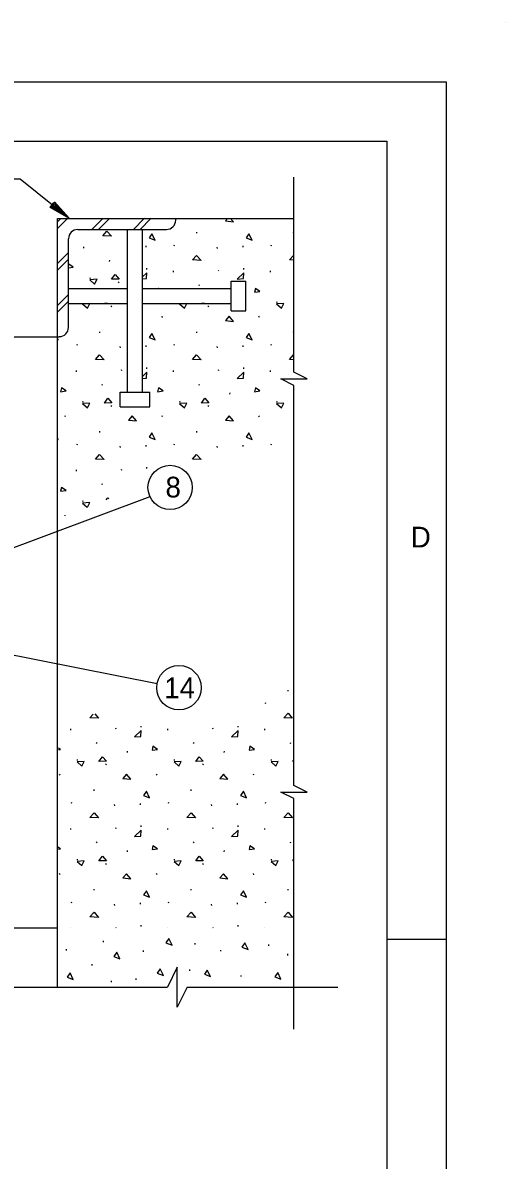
# Model space of a CAD drawing. Extents: x -0.2 to 13.5, y -0.2 to 9.5.
# Drawn here: x 12.14 to 13.5, y 6.294 to 9.5 of the extents above; entities that cross this region are included whole.
import ezdxf

# ---------------------------------------------------------------- set-up
doc = ezdxf.new("R2010")
doc.units = 0
for name, color, linetype in [('Level 1', 7, 'Continuous'), ('Level 10', 7, 'Continuous'), ('Level 13', 7, 'Continuous'), ('Level 2', 7, 'Continuous'), ('Level 3', 7, 'Continuous'), ('Level 50', 7, 'Continuous')]:
    doc.layers.add(name, color=color, linetype=linetype)

msp = doc.modelspace()

# ---------------------------------------------------------------- linework, layer by layer
at = {"layer": 'Level 1'}
msp.add_line((13.1667, 6.9167), (13.3333, 6.9167), dxfattribs=at)
for points in [[(0, 9.3333), (13.3333, 9.3333), (13.3333, 0), (0, 0)], [(0.5, 9.1667), (13.1667, 9.1667), (13.1667, 0.1667), (0.5, 0.1667)]]:
    msp.add_lwpolyline(points, close=True, dxfattribs=at)
msp.add_lwpolyline([(12.6037, 6.7819), (12.5758, 6.7256), (12.5758, 6.838), (12.5477, 6.7819)], dxfattribs=at)
at = {"layer": 'Level 10'}
for p, q in [((12.6306, 8.9066), (12.6304, 8.9097)), ((12.9039, 8.9066), (12.9037, 8.9097)), ((12.3119, 8.865), (12.3119, 8.8688)), ((12.4882, 8.8671), (12.4882, 8.8709)), ((12.567, 8.8716), (12.5675, 8.8744)), ((12.6888, 8.8641), (12.6877, 8.8679)), ((12.7615, 8.8671), (12.7615, 8.8709)), ((12.8404, 8.8716), (12.8409, 8.8744)), ((12.3844, 8.8275), (12.3858, 8.8304)), ((12.4895, 8.8049), (12.4895, 8.8084)), ((12.5647, 8.7969), (12.5647, 8.8006)), ((12.6925, 8.7994), (12.6915, 8.8021)), ((12.7629, 8.8049), (12.7629, 8.8084)), ((12.838, 8.7969), (12.838, 8.8006)), ((12.3304, 8.7795), (12.3307, 8.7823)), ((12.4102, 8.767), (12.4121, 8.7701)), ((12.6373, 8.7594), (12.6387, 8.7623)), ((12.3898, 8.6989), (12.3917, 8.702)), ((12.6631, 8.6989), (12.665, 8.702)), ((12.8566, 8.7114), (12.8569, 8.7141)), ((12.5344, 8.6696), (12.5327, 8.6729)), ((12.8077, 8.6696), (12.806, 8.6729)), ((12.3573, 8.6261), (12.357, 8.6291)), ((12.6306, 8.6261), (12.6304, 8.6291)), ((12.9039, 8.6261), (12.9037, 8.6291)), ((12.2937, 8.591), (12.2942, 8.5938)), ((12.567, 8.591), (12.5675, 8.5938)), ((12.8404, 8.591), (12.8409, 8.5938)), ((12.4155, 8.5836), (12.4144, 8.5873)), ((12.4882, 8.5866), (12.4882, 8.5903)), ((12.6888, 8.5836), (12.6877, 8.5873)), ((12.7615, 8.5866), (12.7615, 8.5903)), ((12.2914, 8.5163), (12.2914, 8.5201)), ((12.4192, 8.5189), (12.4182, 8.5216)), ((12.4895, 8.5244), (12.4895, 8.5279)), ((12.5647, 8.5163), (12.5647, 8.5201)), ((12.6925, 8.5189), (12.6915, 8.5216)), ((12.7629, 8.5244), (12.7629, 8.5279)), ((12.838, 8.5163), (12.838, 8.5201)), ((12.364, 8.4788), (12.3654, 8.4818)), ((12.6373, 8.4788), (12.6387, 8.4818)), ((12.31, 8.4308), (12.3102, 8.4336)), ((12.5833, 8.4308), (12.5835, 8.4336)), ((12.724, 8.4536), (12.7246, 8.4573)), ((12.8566, 8.4308), (12.8569, 8.4336)), ((12.3898, 8.4183), (12.3917, 8.4214)), ((12.6631, 8.4183), (12.665, 8.4214)), ((12.261, 8.3891), (12.2594, 8.3924)), ((12.5344, 8.3891), (12.5327, 8.3924)), ((12.8077, 8.3891), (12.806, 8.3924)), ((12.3573, 8.3455), (12.357, 8.3486)), ((12.6306, 8.3455), (12.6304, 8.3486)), ((12.2937, 8.3104), (12.2942, 8.3133)), ((12.4155, 8.303), (12.4144, 8.3068)), ((12.4882, 8.306), (12.4882, 8.3098)), ((12.567, 8.3104), (12.5675, 8.3133)), ((12.6888, 8.303), (12.6877, 8.3068)), ((12.7615, 8.306), (12.7615, 8.3098)), ((12.8404, 8.3104), (12.8409, 8.3133)), ((12.4192, 8.2383), (12.4182, 8.241)), ((12.4895, 8.2438), (12.4895, 8.2473)), ((12.2914, 8.2358), (12.2914, 8.2395)), ((12.364, 8.1983), (12.3654, 8.2012)), ((12.31, 8.1503), (12.3102, 8.153)), ((12.8882, 7.616), (12.8879, 7.6191)), ((12.8246, 7.5809), (12.8251, 7.5838)), ((12.2757, 7.5063), (12.2757, 7.51)), ((12.4035, 7.5088), (12.4024, 7.5115)), ((12.4738, 7.5143), (12.4738, 7.5178)), ((12.549, 7.5063), (12.549, 7.51)), ((12.6768, 7.5088), (12.6757, 7.5115)), ((12.7471, 7.5143), (12.7471, 7.5178)), ((12.8223, 7.5063), (12.8223, 7.51)), ((12.3482, 7.4688), (12.3496, 7.4717)), ((12.6216, 7.4688), (12.6229, 7.4717)), ((12.8949, 7.4688), (12.8962, 7.4717)), ((12.435, 7.4436), (12.4356, 7.4472)), ((12.7083, 7.4436), (12.7089, 7.4472)), ((12.2942, 7.4208), (12.2945, 7.4235)), ((12.3741, 7.4083), (12.3759, 7.4114)), ((12.5676, 7.4208), (12.5678, 7.4235)), ((12.6474, 7.4083), (12.6492, 7.4114)), ((12.8409, 7.4208), (12.8411, 7.4235)), ((12.2453, 7.379), (12.2436, 7.3823)), ((12.5186, 7.379), (12.5169, 7.3823)), ((12.7919, 7.379), (12.7902, 7.3823)), ((12.3416, 7.3354), (12.3413, 7.3385)), ((12.6149, 7.3354), (12.6146, 7.3385)), ((12.278, 7.3004), (12.2785, 7.3032)), ((12.3997, 7.2929), (12.3987, 7.2967)), ((12.4725, 7.2959), (12.4725, 7.2997)), ((12.5513, 7.3004), (12.5518, 7.3032)), ((12.6731, 7.2929), (12.672, 7.2967)), ((12.7458, 7.2959), (12.7458, 7.2997)), ((12.8246, 7.3004), (12.8251, 7.3032)), ((12.2757, 7.2257), (12.2757, 7.2294)), ((12.4035, 7.2283), (12.4024, 7.2309)), ((12.4738, 7.2338), (12.4738, 7.2373)), ((12.549, 7.2257), (12.549, 7.2294)), ((12.6768, 7.2283), (12.6757, 7.2309)), ((12.7471, 7.2338), (12.7471, 7.2373)), ((12.8223, 7.2257), (12.8223, 7.2294)), ((12.3482, 7.1882), (12.3496, 7.1911)), ((12.6216, 7.1882), (12.6229, 7.1911)), ((12.8949, 7.1882), (12.8962, 7.1911)), ((12.435, 7.163), (12.4356, 7.1666)), ((12.7083, 7.163), (12.7089, 7.1666)), ((12.2942, 7.1402), (12.2945, 7.1429)), ((12.3741, 7.1277), (12.3759, 7.1308)), ((12.5676, 7.1402), (12.5678, 7.1429)), ((12.6474, 7.1277), (12.6492, 7.1308)), ((12.8409, 7.1402), (12.8411, 7.1429)), ((12.2453, 7.0984), (12.2436, 7.1018)), ((12.5186, 7.0984), (12.5169, 7.1018)), ((12.7919, 7.0984), (12.7902, 7.1018)), ((12.3416, 7.0549), (12.3413, 7.0579)), ((12.6149, 7.0549), (12.6146, 7.0579)), ((12.8882, 7.0549), (12.8879, 7.0579)), ((12.278, 7.0198), (12.2785, 7.0226)), ((12.5513, 7.0198), (12.5518, 7.0226)), ((12.8246, 7.0198), (12.8251, 7.0226)), ((12.3997, 7.0124), (12.3987, 7.0161)), ((12.4725, 7.0154), (12.4725, 7.0191)), ((12.6731, 7.0124), (12.672, 7.0161)), ((12.7458, 7.0154), (12.7458, 7.0191)), ((12.4738, 6.9532), (12.4738, 6.9567)), ((12.7471, 6.9532), (12.7471, 6.9567)), ((12.3675, 6.9083), (12.3675, 6.912)), ((12.6265, 6.9021), (12.6265, 6.9059)), ((12.8335, 6.8981), (12.8335, 6.9018)), ((12.2635, 6.8848), (12.2635, 6.8886)), ((12.4807, 6.8817), (12.4807, 6.8855)), ((12.6989, 6.8828), (12.6989, 6.8865)), ((12.8875, 6.8715), (12.8875, 6.8753)), ((12.3359, 6.843), (12.3359, 6.8467)), ((12.6112, 6.8277), (12.6112, 6.8314)), ((12.3899, 6.7961), (12.3899, 6.7998)), ((12.4603, 6.8022), (12.4603, 6.8059)), ((12.756, 6.8114), (12.756, 6.8151))]:
    msp.add_line(p, q, dxfattribs=at)
for points in [[(12.7152, 8.9456), (12.7117, 8.9414)], [(12.734, 8.9389), (12.728, 8.9458)], [(12.7117, 8.9414), (12.734, 8.9389)], [(12.2699, 8.8194), (12.2692, 8.8164)], [(12.2826, 8.8108), (12.2699, 8.8194)], [(12.8917, 8.8316), (12.9035, 8.8444)], [(12.9046, 8.8308), (12.8917, 8.8316)], [(12.9035, 8.8444), (12.9046, 8.8433)], [(12.2692, 8.8091), (12.2826, 8.8108)], [(12.4895, 8.7956), (12.4775, 8.7838)], [(12.4886, 8.7789), (12.4895, 8.7956)], [(12.4775, 8.778), (12.4886, 8.7789)], [(12.5227, 8.7513), (12.5226, 8.7506)], [(12.5237, 8.7506), (12.5227, 8.7513)], [(12.3702, 8.7088), (12.3703, 8.709)], [(12.3791, 8.709), (12.3702, 8.7088)], [(12.6435, 8.7088), (12.6436, 8.709)], [(12.6524, 8.709), (12.6435, 8.7088)], [(12.2401, 8.6062), (12.2379, 8.6107)], [(12.2379, 8.607), (12.2401, 8.6062)], [(12.8917, 8.551), (12.9035, 8.5639)], [(12.9035, 8.5639), (12.9046, 8.5627)], [(12.9046, 8.5503), (12.8917, 8.551)], [(12.4895, 8.515), (12.4775, 8.5033)], [(12.4775, 8.4975), (12.4886, 8.4983)], [(12.4886, 8.4983), (12.4895, 8.515)], [(12.2401, 8.3256), (12.2381, 8.3297)], [(12.2381, 8.3264), (12.2401, 8.3256)], [(12.3295, 8.1476), (12.309, 8.1462)], [(12.309, 8.1462), (12.3222, 8.1344)], [(12.3225, 8.1345), (12.3295, 8.1476)], [(12.3757, 8.155), (12.3802, 8.1609)], [(12.3802, 8.1609), (12.383, 8.1578)], [(12.2599, 8.1107), (12.2594, 8.1118)], [(12.3293, 7.5409), (12.3387, 7.5511)], [(12.3539, 7.5396), (12.3293, 7.5409)], [(12.3429, 7.5519), (12.3539, 7.5396)], [(12.8759, 7.5409), (12.8878, 7.5538)], [(12.8999, 7.5396), (12.8759, 7.5409)], [(12.8878, 7.5538), (12.8998, 7.5404)], [(12.2464, 7.4521), (12.2412, 7.4556)], [(12.2412, 7.4514), (12.2464, 7.4521)], [(12.9011, 7.4181), (12.9031, 7.4209)], [(12.9032, 7.4182), (12.9011, 7.4181)], [(12.2464, 7.1715), (12.2394, 7.1762)], [(12.2394, 7.1706), (12.2464, 7.1715)], [(12.9011, 7.1376), (12.9046, 7.1422)], [(12.9046, 7.1376), (12.9011, 7.1376)], [(12.2757, 6.9486), (12.2757, 6.9489)], [(12.4032, 6.9486), (12.4024, 6.9504)], [(12.549, 6.9486), (12.549, 6.9489)], [(12.6765, 6.9486), (12.6757, 6.9504)], [(12.8223, 6.9486), (12.8223, 6.9489)]]:
    msp.add_lwpolyline(points, dxfattribs=at)
for points in [[(12.3655, 8.8997), (12.3774, 8.9126), (12.3901, 8.8983)], [(12.4964, 8.8934), (12.5134, 8.8868), (12.5044, 8.9052)], [(12.7697, 8.8934), (12.7867, 8.8868), (12.7777, 8.9052)], [(12.6184, 8.8316), (12.6302, 8.8444), (12.643, 8.8302)], [(12.3906, 8.7769), (12.4007, 8.7902), (12.412, 8.7774)], [(12.7619, 8.7789), (12.7629, 8.7956), (12.7444, 8.7775)], [(12.3295, 8.7754), (12.3428, 8.7636), (12.3499, 8.7769)], [(12.7936, 8.7408), (12.8088, 8.7427), (12.796, 8.7513)], [(12.309, 8.7073), (12.3224, 8.6954), (12.3295, 8.7088)], [(12.5824, 8.7073), (12.5957, 8.6954), (12.6028, 8.7088)], [(12.8557, 8.7073), (12.869, 8.6954), (12.8761, 8.7088)], [(12.734, 8.6584), (12.7216, 8.6726), (12.7117, 8.6608)], [(12.4964, 8.6128), (12.5134, 8.6062), (12.5044, 8.6246)], [(12.7697, 8.6128), (12.7867, 8.6062), (12.7777, 8.6246)], [(12.345, 8.551), (12.3569, 8.5639), (12.3697, 8.5496)], [(12.6184, 8.551), (12.6302, 8.5639), (12.643, 8.5496)], [(12.7619, 8.4983), (12.7629, 8.515), (12.7444, 8.4969)], [(12.247, 8.4602), (12.2622, 8.4621), (12.2494, 8.4707)], [(12.5203, 8.4602), (12.5355, 8.4621), (12.5227, 8.4707)], [(12.7936, 8.4602), (12.8088, 8.4621), (12.796, 8.4707)], [(12.3702, 8.4282), (12.3802, 8.4415), (12.3915, 8.4287)], [(12.6435, 8.4282), (12.6535, 8.4415), (12.6649, 8.4287)], [(12.309, 8.4268), (12.3224, 8.4149), (12.3295, 8.4282)], [(12.5824, 8.4268), (12.5957, 8.4149), (12.6028, 8.4282)], [(12.8557, 8.4268), (12.869, 8.4149), (12.8761, 8.4282)], [(12.4607, 8.3778), (12.4483, 8.3921), (12.4384, 8.3803)], [(12.734, 8.3778), (12.7216, 8.3921), (12.7117, 8.3803)], [(12.4964, 8.3323), (12.5134, 8.3256), (12.5044, 8.3441)], [(12.7697, 8.3323), (12.7867, 8.3256), (12.7777, 8.3441)], [(12.345, 8.2704), (12.3569, 8.2833), (12.3697, 8.2691)], [(12.6184, 8.2704), (12.6302, 8.2833), (12.643, 8.2691)], [(12.247, 8.1796), (12.2622, 8.1816), (12.2494, 8.1901)], [(12.4729, 7.4883), (12.4738, 7.5049), (12.4553, 7.4869)], [(12.7462, 7.4883), (12.7471, 7.5049), (12.7286, 7.4869)], [(12.5046, 7.4501), (12.5197, 7.4521), (12.507, 7.4606)], [(12.7779, 7.4501), (12.7931, 7.4521), (12.7803, 7.4606)], [(12.2933, 7.4167), (12.3066, 7.4048), (12.3137, 7.4181)], [(12.3544, 7.4181), (12.3645, 7.4314), (12.3758, 7.4186)], [(12.5666, 7.4167), (12.5799, 7.4048), (12.5871, 7.4181)], [(12.6277, 7.4181), (12.6378, 7.4314), (12.6491, 7.4186)], [(12.8399, 7.4167), (12.8532, 7.4048), (12.8604, 7.4181)], [(12.4449, 7.3678), (12.4326, 7.382), (12.4226, 7.3702)], [(12.7182, 7.3678), (12.7059, 7.382), (12.6959, 7.3702)], [(12.4806, 7.3222), (12.4977, 7.3156), (12.4887, 7.334)], [(12.7539, 7.3222), (12.771, 7.3156), (12.762, 7.334)], [(12.3293, 7.2604), (12.3412, 7.2733), (12.3539, 7.259)], [(12.6026, 7.2604), (12.6145, 7.2733), (12.6272, 7.259)], [(12.8759, 7.2604), (12.8878, 7.2733), (12.9006, 7.259)], [(12.4729, 7.2077), (12.4738, 7.2244), (12.4553, 7.2063)], [(12.7462, 7.2077), (12.7471, 7.2244), (12.7286, 7.2063)], [(12.3544, 7.1376), (12.3645, 7.1509), (12.3758, 7.1381)], [(12.5046, 7.1696), (12.5197, 7.1715), (12.507, 7.1801)], [(12.6277, 7.1376), (12.6378, 7.1509), (12.6491, 7.1381)], [(12.7779, 7.1696), (12.7931, 7.1715), (12.7803, 7.1801)], [(12.2933, 7.1361), (12.3066, 7.1243), (12.3137, 7.1376)], [(12.5666, 7.1361), (12.5799, 7.1243), (12.5871, 7.1376)], [(12.8399, 7.1361), (12.8532, 7.1243), (12.8604, 7.1376)], [(12.4449, 7.0872), (12.4326, 7.1014), (12.4226, 7.0896)], [(12.7182, 7.0872), (12.7059, 7.1014), (12.6959, 7.0896)], [(12.4806, 7.0416), (12.4977, 7.035), (12.4887, 7.0534)], [(12.7539, 7.0416), (12.771, 7.035), (12.762, 7.0534)], [(12.3293, 6.9798), (12.3412, 6.9927), (12.3539, 6.9784)], [(12.6026, 6.9798), (12.6145, 6.9927), (12.6272, 6.9784)], [(12.8759, 6.9798), (12.8878, 6.9927), (12.9006, 6.9784)], [(12.5439, 6.907), (12.5609, 6.9003), (12.5519, 6.9188)], [(12.758, 6.8947), (12.7751, 6.8881), (12.7661, 6.9065)], [(12.397, 6.8682), (12.4141, 6.8616), (12.4051, 6.88)], [(12.5194, 6.8213), (12.5365, 6.8146), (12.5275, 6.8331)], [(12.652, 6.8182), (12.669, 6.8116), (12.66, 6.83)], [(12.2655, 6.8101), (12.2826, 6.8034), (12.2736, 6.8219)], [(12.8508, 6.8111), (12.8679, 6.8044), (12.8589, 6.8229)]]:
    msp.add_lwpolyline(points, close=True, dxfattribs=at)
at = {"layer": 'Level 13'}
for points in [[(12.9046, 8.4774), (12.8671, 8.496), (12.942, 8.496), (12.9046, 8.5148)], [(12.9046, 7.3131), (12.8671, 7.3318), (12.942, 7.3318), (12.9046, 7.3505)]]:
    msp.add_lwpolyline(points, dxfattribs=at)
at = {"layer": 'Level 2'}
for p, q in [((12.9046, 8.5148), (12.9046, 9.0647)), ((12.2379, 8.9486), (12.9046, 8.9486)), ((12.2379, 6.7819), (12.2379, 8.9486)), ((12.5713, 8.9433), (12.5713, 8.9486)), ((12.2952, 8.9173), (12.5452, 8.9173)), ((12.4358, 8.459), (12.4358, 8.9173)), ((12.4775, 8.459), (12.4775, 8.9173)), ((12.2692, 8.6413), (12.2692, 8.8913)), ((12.7275, 8.6881), (12.7275, 8.7715)), ((12.7275, 8.7715), (12.7692, 8.7715)), ((12.7692, 8.6881), (12.7692, 8.7715)), ((12.2692, 8.7506), (12.4358, 8.7506)), ((12.4775, 8.7506), (12.7275, 8.7506)), ((12.2692, 8.709), (12.4358, 8.709)), ((12.4775, 8.709), (12.7275, 8.709)), ((12.7275, 8.6881), (12.7692, 8.6881)), ((10.5713, 8.6152), (12.2379, 8.6152)), ((12.2379, 8.6152), (12.2431, 8.6152)), ((12.9046, 7.3505), (12.9046, 8.4774)), ((12.415, 8.459), (12.4983, 8.459)), ((12.415, 8.4173), (12.415, 8.459)), ((12.4983, 8.4173), (12.4983, 8.459)), ((12.415, 8.4173), (12.4983, 8.4173)), ((12.9046, 6.6633), (12.9046, 7.3131)), ((10.5713, 6.9486), (12.2379, 6.9486)), ((12.0624, 6.7819), (12.5477, 6.7819)), ((12.6037, 6.7819), (13.0285, 6.7819))]:
    msp.add_line(p, q, dxfattribs=at)
for points in [[(12.2378, 8.9199), (12.2665, 8.9486)], [(12.2379, 8.9388), (12.2476, 8.9486)], [(12.3335, 8.9166), (12.3656, 8.9487)], [(12.3523, 8.9166), (12.3845, 8.9487)], [(12.4513, 8.9166), (12.4836, 8.9488)], [(12.4702, 8.9166), (12.5025, 8.9488)], [(12.2376, 8.8207), (12.2682, 8.8513)], [(12.2375, 8.8018), (12.2682, 8.8324)], [(12.2373, 8.7025), (12.2682, 8.7334)], [(12.2372, 8.6836), (12.2682, 8.7146)]]:
    msp.add_lwpolyline(points, dxfattribs=at)
for centre, start, end in [((12.2952, 8.8913), 90, 180), ((12.5452, 8.9433), 270, 0), ((12.2431, 8.6413), 270, 0)]:
    msp.add_arc(centre, 0.026, start, end, dxfattribs=at)
at = {"layer": 'Level 3'}
for p, q in [((13.5, 9.5), (13.5, 9.5)), ((12.4983, 8.1642), (11.7624, 7.8878)), ((11.7351, 7.7928), (12.5192, 7.6379))]:
    msp.add_line(p, q, dxfattribs=at)
msp.add_lwpolyline([(12.0323, 9.0603), (12.1326, 9.0603), (12.2722, 8.9486)], dxfattribs=at)
for centre in [(12.5556, 8.1902), (12.5805, 7.6258)]:
    msp.add_circle(centre, 0.0625, dxfattribs=at)
at = {"layer": 'Level 50'}
for p, q in [((12.2587, 8.9594), (12.2587, 8.9594)), ((12.2722, 8.9486), (12.2722, 8.9486))]:
    msp.add_line(p, q, dxfattribs=at)
msp.add_lwpolyline([(12.23, 8.9956), (12.2722, 8.9486), (12.2171, 8.9794), (12.2282, 8.9932), (12.2587, 8.9594), (12.2213, 8.9804), (12.2284, 8.9892), (12.2457, 8.9698), (12.2254, 8.9813), (12.2284, 8.9849), (12.2322, 8.9806)], dxfattribs=at)

# ---------------------------------------------------------------- texts
at = {"layer": 'Level 1'}
msp.add_text('D', height=0.0584, dxfattribs=at).set_placement((13.2337, 8.0211))
at = {"layer": 'Level 3'}
for s, height, p in [('8', 0.0583, (12.5425, 8.1621)), ('14', 0.05833, (12.5388, 7.5963))]:
    msp.add_text(s, height=height, dxfattribs=at).set_placement(p)

doc.saveas('drawing.dxf')
